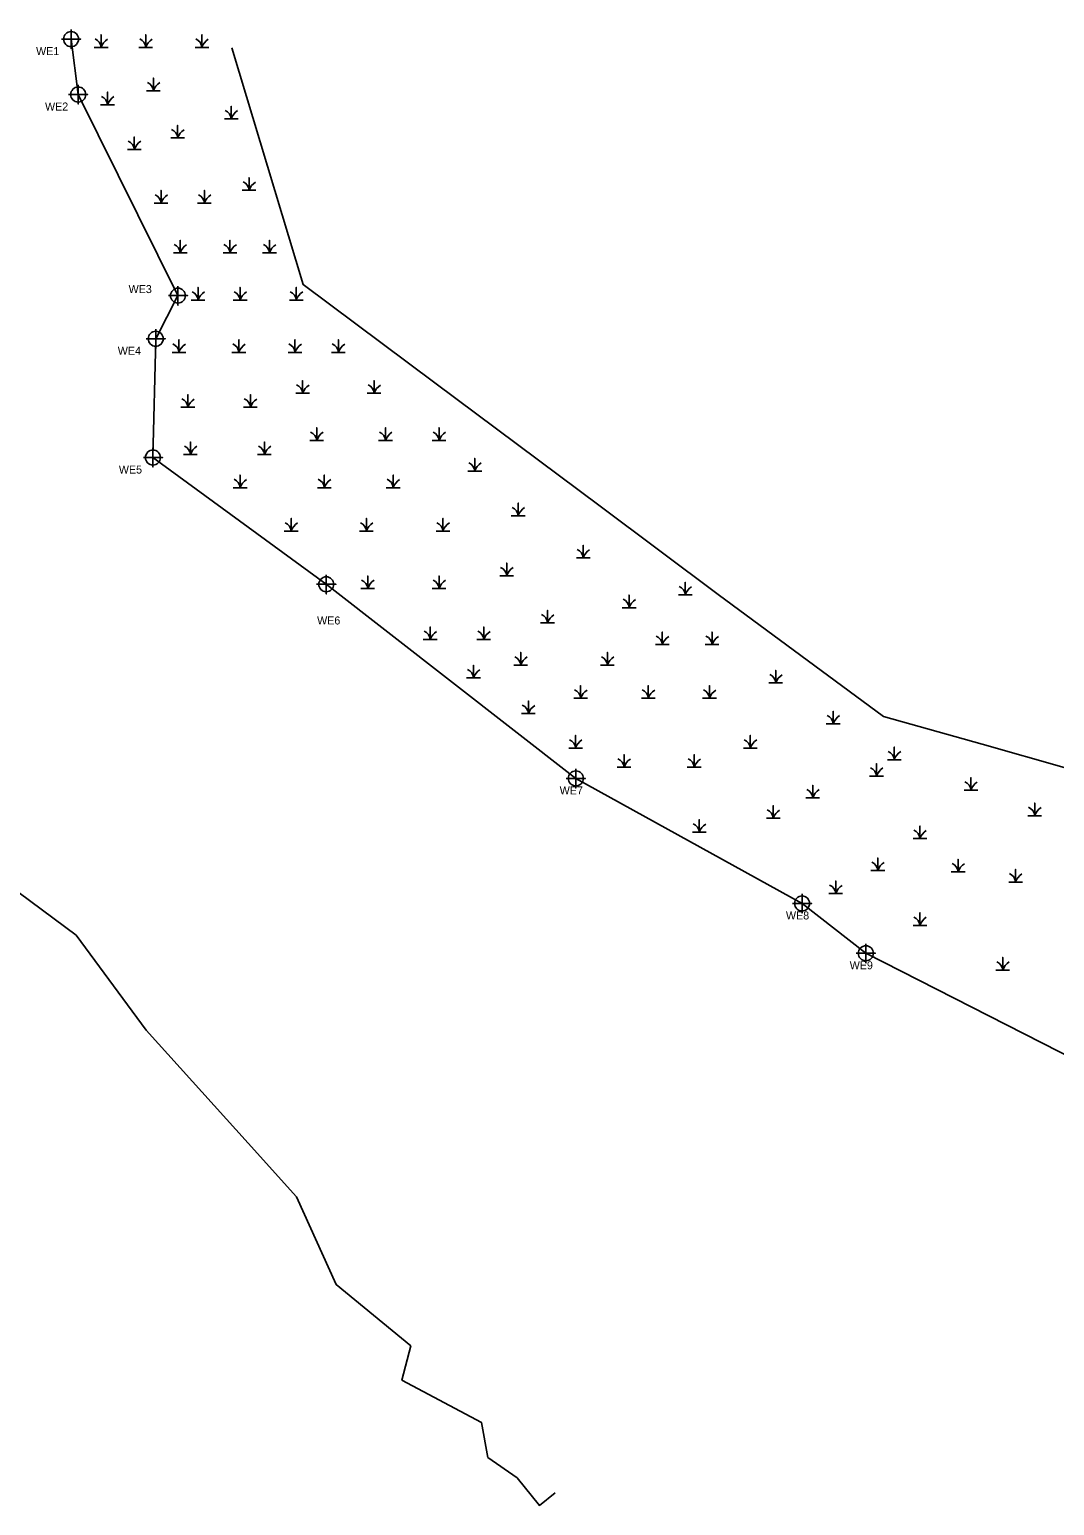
# Model space of a CAD drawing. Extents: x 2603618 to 2605510, y 618189 to 619022.
# Drawn here: x 2604875.2 to 2605195.6, y 618372.9 to 618834.1 of the extents above; entities that cross this region are included whole.
import ezdxf

# ---------------------------------------------------------------- set-up
doc = ezdxf.new("R2010")
doc.units = 0
for name, color, linetype in [('Exist Environmental Wetland Boundary', 7, 'Continuous'), ('Exist Environmental Wetland Boundary Cogo Comment', 7, 'Continuous'), ('Exist Environmental Wetland Boundary Cogo Point CELL', 7, 'Continuous'), ('Exist Hydro Jurisdictional Stream or Body of Water Mitigable', 7, 'Continuous'), ('Exist Hydro Swamp or Marsh', 7, 'Continuous')]:
    doc.layers.add(name, color=color, linetype=linetype)

# ---------------------------------------------------------------- blocks, each defined once
blk = doc.blocks.new('Exist Hydro Swamp or Marsh')
at = {"layer": 'Exist Hydro Swamp or Marsh'}
blk.add_line((0, 0), (0, 0), dxfattribs=at)
blk.add_lwpolyline([(-0.043, -0.0357), (0, -0.0357), (0, 0.0432), (0, -0.0357), (0.043, -0.0357)], dxfattribs=at)
for centre, radius, start, end in [((-0.0613, -0.0401), 0.0615, 4.14034, 67.53497), ((0.0912, -0.066), 0.0961, 122.12745, 161.62219)]:
    blk.add_arc(centre, radius, start, end, dxfattribs=at)

msp = doc.modelspace()

# ---------------------------------------------------------------- linework, layer by layer
at = {"layer": 'Exist Environmental Wetland Boundary'}
msp.add_lwpolyline([(2604888.21, 618831.09), (2604890.44, 618813.78), (2604921.62, 618750.94), (2604914.66, 618737.46), (2604913.79, 618700.35), (2604967.96, 618660.73), (2605045.97, 618600.08), (2605116.69, 618561), (2605136.62, 618545.44), (2605202.62, 618511.85), (2605271.25, 618516.23), (2605348.67, 618522.43), (2605407.29, 618531.73), (2605437.37, 618555.56), (2605459.86, 618578.52), (2605498.99, 618616.91)], dxfattribs=at)
at = {"layer": 'Exist Environmental Wetland Boundary Cogo Point CELL'}
for points in [[(2604888.21, 618834.09), (2604888.21, 618828.09), (2604888.21, 618831.09), (2604891.21, 618831.09), (2604885.21, 618831.09)], [(2604890.44, 618816.78), (2604890.44, 618810.78), (2604890.44, 618813.78), (2604893.44, 618813.78), (2604887.44, 618813.78)], [(2604921.62, 618753.94), (2604921.62, 618747.94), (2604921.62, 618750.94), (2604924.62, 618750.94), (2604918.62, 618750.94)], [(2604914.66, 618740.46), (2604914.66, 618734.46), (2604914.66, 618737.46), (2604917.66, 618737.46), (2604911.66, 618737.46)], [(2604913.79, 618703.35), (2604913.79, 618697.35), (2604913.79, 618700.35), (2604916.79, 618700.35), (2604910.79, 618700.35)], [(2604967.96, 618663.73), (2604967.96, 618657.73), (2604967.96, 618660.73), (2604970.96, 618660.73), (2604964.96, 618660.73)], [(2605045.97, 618603.08), (2605045.97, 618597.08), (2605045.97, 618600.08), (2605048.97, 618600.08), (2605042.97, 618600.08)], [(2605116.69, 618564), (2605116.69, 618558), (2605116.69, 618561), (2605119.69, 618561), (2605113.69, 618561)], [(2605136.62, 618548.44), (2605136.62, 618542.44), (2605136.62, 618545.44), (2605139.62, 618545.44), (2605133.62, 618545.44)]]:
    msp.add_lwpolyline(points, dxfattribs=at)
for centre in [(2604888.21, 618831.09), (2604890.44, 618813.78), (2604921.62, 618750.94), (2604914.66, 618737.46), (2604913.79, 618700.35), (2604967.96, 618660.73), (2605045.97, 618600.08), (2605116.69, 618561), (2605136.62, 618545.44)]:
    msp.add_circle(centre, 2.34, dxfattribs=at)
at = {"layer": 'Exist Hydro Jurisdictional Stream or Body of Water Mitigable'}
for points in [[(2604938.42, 618828.36), (2604949.58, 618791.37), (2604960.74, 618754.38), (2605001.9, 618723.67), (2605053.56, 618685.12), (2605090.48, 618657.58)], [(2605090.48, 618657.58), (2605116.3, 618638.53), (2605142.12, 618619.47), (2605173, 618610.74), (2605225.68, 618595.83), (2605258.13, 618586.65), (2605274.65, 618599.44)], [(2604838.54, 618617.4), (2604857.9, 618589.82), (2604872.03, 618564.3), (2604889.79, 618551.08), (2604911.66, 618521.46), (2604943.55, 618486.13), (2604958.7, 618469.35)], [(2604958.7, 618469.35), (2604971.11, 618441.92), (2604994.35, 618422.79), (2604991.61, 618412.07), (2605016.44, 618398.85), (2605018.49, 618387.91), (2605027.62, 618381.55), (2605034.6, 618372.89), (2605039.47, 618376.81)]]:
    msp.add_lwpolyline(points, dxfattribs=at)

# ---------------------------------------------------------------- block references
at = {"layer": 'Exist Hydro Swamp or Marsh', "xscale": 50, "yscale": 50}
for p in [(2604897.6, 618830.3), (2604911.55, 618830.3), (2604929.09, 618830.3), (2604913.95, 618816.74), (2604899.6, 618812.36), (2604938.26, 618807.97), (2604921.52, 618801.99), (2604907.97, 618798.4), (2604943.84, 618785.64), (2604916.34, 618781.65), (2604929.89, 618781.65), (2604922.32, 618766.09), (2604937.86, 618766.09), (2604950.22, 618766.09), (2604927.9, 618751.34), (2604941.05, 618751.34), (2604958.59, 618751.34), (2604921.92, 618734.99), (2604940.65, 618734.99), (2604958.19, 618734.99), (2604971.75, 618734.99), (2604960.58, 618722.22), (2604982.91, 618722.22), (2604924.71, 618717.84), (2604944.24, 618717.84), (2604964.97, 618707.47), (2604986.49, 618707.47), (2605003.24, 618707.47), (2604925.51, 618703.08), (2604948.63, 618703.08), (2605014.4, 618697.9), (2604941.05, 618692.71), (2604967.36, 618692.71), (2604988.89, 618692.71), (2605027.95, 618683.94), (2604957, 618679.15), (2604980.51, 618679.15), (2605004.43, 618679.15), (2605048.28, 618670.78), (2605024.36, 618665.19), (2604980.91, 618661.21), (2605003.24, 618661.21), (2605080.17, 618659.21), (2605062.63, 618655.22), (2605037.12, 618650.44), (2605000.45, 618645.25), (2605017.19, 618645.25), (2605072.99, 618643.66), (2605088.54, 618643.66), (2605028.75, 618637.28), (2605055.85, 618637.28), (2605014, 618633.29), (2605108.47, 618631.69), (2605047.48, 618626.91), (2605068.61, 618626.91), (2605087.74, 618626.91), (2605031.14, 618622.12), (2605126.41, 618618.93), (2605045.89, 618611.35), (2605100.5, 618611.35), (2605145.5, 618607.7), (2605061.03, 618605.37), (2605082.96, 618605.37), (2605139.96, 618602.58), (2605120.03, 618595.8), (2605169.46, 618598.19), (2605107.67, 618589.42), (2605189.39, 618590.22), (2605084.55, 618585.03), (2605153.51, 618583.04), (2605140.36, 618573.07), (2605165.47, 618572.67), (2605183.41, 618569.48), (2605127.2, 618565.89), (2605153.51, 618555.92), (2605179.42, 618541.96)]:
    msp.add_blockref('Exist Hydro Swamp or Marsh', p, dxfattribs=at)

# ---------------------------------------------------------------- texts
at = {"layer": 'Exist Environmental Wetland Boundary Cogo Comment'}
for s, p in [('WE1', (2604877.27, 618826.09)), ('WE2', (2604880.06, 618808.78)), ('WE3', (2604906.19, 618751.74)), ('WE4', (2604902.8, 618732.46)), ('WE5', (2604903.14, 618695.35)), ('WE6', (2604965.11, 618648.18)), ('WE7', (2605040.93, 618595.08)), ('WE8', (2605111.65, 618556)), ('WE9', (2605131.58, 618540.44))]:
    msp.add_text(s, height=2.5, dxfattribs=at).set_placement(p)

doc.saveas('drawing.dxf')
